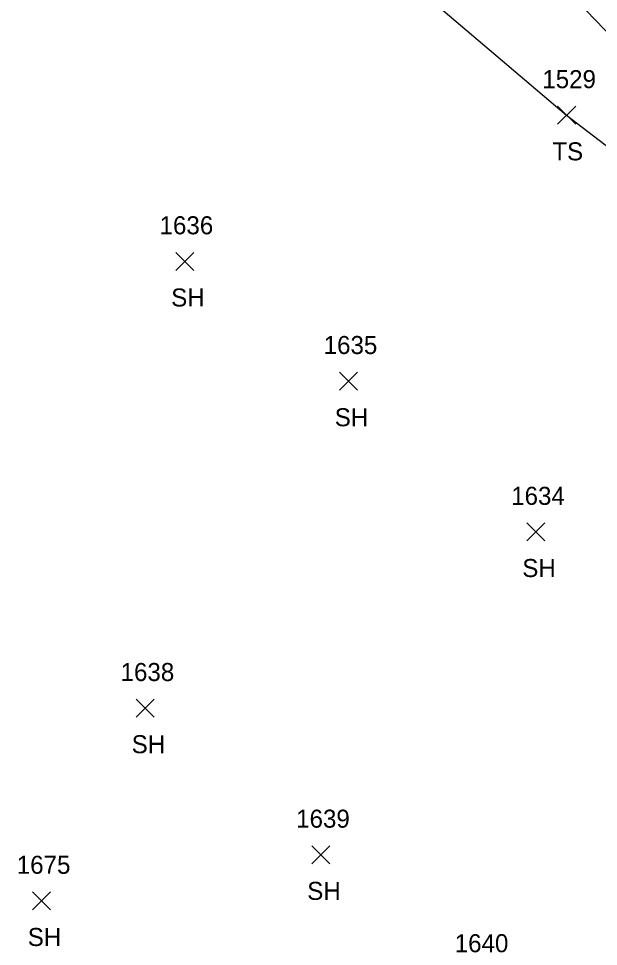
# Model space of a CAD drawing. Extents: x 1520648 to 1523413, y 732854 to 735518.
# Drawn here: x 1522197.5 to 1522261.7, y 734108.7 to 734211.6 of the extents above; entities that cross this region are included whole.
import ezdxf

# ---------------------------------------------------------------- set-up
doc = ezdxf.new("R2010")
doc.units = 0
for name, color, linetype in [('L_A', 7, 'Continuous'), ('L_I', 7, 'Continuous'), ('L_TIC', 7, 'Continuous'), ('LELB', 7, 'Continuous')]:
    doc.layers.add(name, color=color, linetype=linetype)

msp = doc.modelspace()

# ---------------------------------------------------------------- linework, layer by layer
at = {"layer": 'L_TIC'}
for points in [[(1522257.22, 734199.84), (1522259.22, 734201.84)], [(1522259.22, 734199.84), (1522257.22, 734201.84)], [(1522214.89, 734183.65), (1522216.89, 734185.65)], [(1522216.89, 734183.65), (1522214.89, 734185.65)], [(1522233.02, 734170.38), (1522235.02, 734172.38)], [(1522235.02, 734170.38), (1522233.02, 734172.38)], [(1522253.81, 734153.67), (1522255.81, 734155.67)], [(1522255.81, 734153.67), (1522253.81, 734155.67)], [(1522210.51, 734134.15), (1522212.51, 734136.15)], [(1522212.51, 734134.15), (1522210.51, 734136.15)], [(1522229.98, 734117.9), (1522231.98, 734119.9)], [(1522231.98, 734117.9), (1522229.98, 734119.9)], [(1522199, 734112.79), (1522201, 734114.79)], [(1522201, 734112.79), (1522199, 734114.79)]]:
    msp.add_lwpolyline(points, dxfattribs=at)
at = {"layer": 'LELB'}
for points in [[(1522244.93, 734228.52), (1522263.32, 734209.37), (1522289.49, 734189.74), (1522306.79, 734166.34), (1522312.53, 734155.32), (1522317.63, 734143.65), (1522298.72, 734121.6), (1522271.83, 734089.82), (1522252.2, 734066.84), (1522225.77, 734033.34), (1522220.1, 734019.64), (1522210.97, 733988.14), (1522200.09, 733970.45)], [(1522237.38, 734218.53), (1522258.22, 734200.84), (1522283.25, 734181.69), (1522301.32, 734163.17), (1522304.68, 734146.8), (1522288.26, 734129.35), (1522261.48, 734094.25), (1522252.67, 734080.33), (1522245.86, 734070.77), (1522213.93, 734029.6), (1522209.42, 734024), (1522201.64, 733983.59), (1522200.09, 733970.45), (1522202, 733964.19)]]:
    msp.add_lwpolyline(points, dxfattribs=at)

# ---------------------------------------------------------------- texts
at = {"layer": 'L_A'}
for s, p in [('TS', (1522256.63, 734195.84)), ('SH', (1522214.38, 734179.65)), ('SH', (1522232.51, 734166.38)), ('SH', (1522253.3, 734149.67)), ('SH', (1522210, 734130.15)), ('SH', (1522229.46, 734113.9)), ('SH', (1522198.48, 734108.79))]:
    msp.add_text(s, height=2, dxfattribs=at).set_placement(p)
at = {"layer": 'L_I'}
for s, p in [('1529', (1522255.52, 734203.84)), ('1636', (1522213.09, 734187.65)), ('1635', (1522231.28, 734174.38)), ('1634', (1522252.07, 734157.67)), ('1638', (1522208.77, 734138.15)), ('1639', (1522228.23, 734121.9)), ('1675', (1522197.26, 734116.79)), ('1640', (1522245.81, 734108.1))]:
    msp.add_text(s, height=2, dxfattribs=at).set_placement(p)

doc.saveas('drawing.dxf')
